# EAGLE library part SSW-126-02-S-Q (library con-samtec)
THROUGH-HOLE .025" SQ POST SOCKET Source: Samtec SSW.pdf
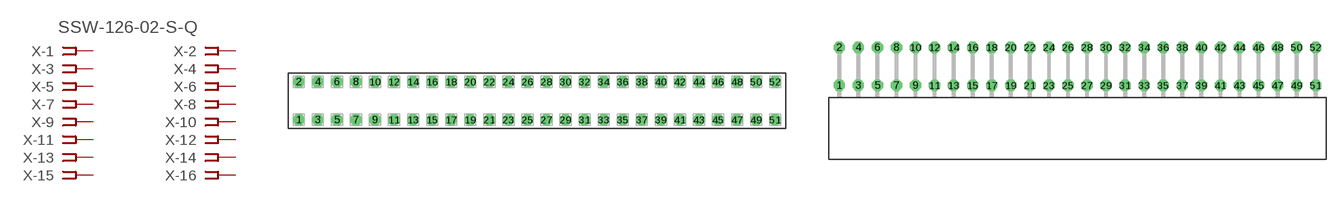
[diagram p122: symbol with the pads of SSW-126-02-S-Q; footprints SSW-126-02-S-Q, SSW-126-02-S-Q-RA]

Designator prefix X; gates -1=FPINV -2=FPIN -3=FPIN -4=FPIN -5=FPIN -6=FPIN -7=FPIN -8=FPIN -9=FPIN -10=FPIN -11=FPIN -12=FPIN -13=FPIN -14=FPIN -15=FPIN -16=FPIN -17=FPIN -18=FPIN -19=FPIN -20=FPIN -21=FPIN -22=FPIN -23=FPIN -24=FPIN -25=FPIN -26=FPIN -27=FPIN -28=FPIN -29=FPIN -30=FPIN -31=FPIN -32=FPIN -33=FPIN -34=FPIN -35=FPIN -36=FPIN -37=FPIN -38=FPIN -39=FPIN -40=FPIN -41=FPIN -42=FPIN -43=FPIN -44=FPIN -45=FPIN -46=FPIN -47=FPIN -48=FPIN -49=FPIN -50=FPIN -51=FPIN -52=FPIN

## SSW-126-02-S-Q (OC_FARNELL: unknown; OC_NEWARK: unknown)  [SSW-126-02-S-Q]
1  -1:1  pas
2  -2:1  pas
3  -3:1  pas
4  -4:1  pas
5  -5:1  pas
6  -6:1  pas
7  -7:1  pas
8  -8:1  pas
9  -9:1  pas
10  -10:1  pas
11  -11:1  pas
12  -12:1  pas
13  -13:1  pas
14  -14:1  pas
15  -15:1  pas
16  -16:1  pas
17  -17:1  pas
18  -18:1  pas
19  -19:1  pas
20  -20:1  pas
21  -21:1  pas
22  -22:1  pas
23  -23:1  pas
24  -24:1  pas
25  -25:1  pas
26  -26:1  pas
27  -27:1  pas
28  -28:1  pas
29  -29:1  pas
30  -30:1  pas
31  -31:1  pas
32  -32:1  pas
33  -33:1  pas
34  -34:1  pas
35  -35:1  pas
36  -36:1  pas
37  -37:1  pas
38  -38:1  pas
39  -39:1  pas
40  -40:1  pas
41  -41:1  pas
42  -42:1  pas
43  -43:1  pas
44  -44:1  pas
45  -45:1  pas
46  -46:1  pas
47  -47:1  pas
48  -48:1  pas
49  -49:1  pas
50  -50:1  pas
51  -51:1  pas
52  -52:1  pas

## SSW-126-02-S-QRA (OC_FARNELL: unknown; OC_NEWARK: unknown)  [SSW-126-02-S-Q-RA]
Pads as for SSW-126-02-S-Q

## Footprint SSW-126-02-S-Q (pad centres in mm)
THROUGH-HOLE .025" SQ POST SOCKET Source: Samtec SSW.pdf
drill 1 pad 1.5 octagon: 1 -31.75,-2.54; 2 -31.75,2.54; 3 -29.21,-2.54; 4 -29.21,2.54; 5 -26.67,-2.54; 6 -26.67,2.54; 7 -24.13,-2.54; 8 -24.13,2.54; 9 -21.59,-2.54; 10 -21.59,2.54; 11 -19.05,-2.54; 12 -19.05,2.54; 13 -16.51,-2.54; 14 -16.51,2.54; 15 -13.97,-2.54; 16 -13.97,2.54; 17 -11.43,-2.54; 18 -11.43,2.54; 19 -8.89,-2.54; 20 -8.89,2.54; 21 -6.35,-2.54; 22 -6.35,2.54; 23 -3.81,-2.54; 24 -3.81,2.54; 25 -1.27,-2.54; 26 -1.27,2.54; 27 1.27,-2.54; 28 1.27,2.54; 29 3.81,-2.54; 30 3.81,2.54; 31 6.35,-2.54; 32 6.35,2.54; 33 8.89,-2.54; 34 8.89,2.54; 35 11.43,-2.54; 36 11.43,2.54; 37 13.97,-2.54; 38 13.97,2.54; 39 16.51,-2.54; 40 16.51,2.54; 41 19.05,-2.54; 42 19.05,2.54; 43 21.59,-2.54; 44 21.59,2.54; 45 24.13,-2.54; 46 24.13,2.54; 47 26.67,-2.54; 48 26.67,2.54; 49 29.21,-2.54; 50 29.21,2.54; 51 31.75,-2.54; 52 31.75,2.54

## Footprint SSW-126-02-S-Q-RA (pad centres in mm)
THROUGH-HOLE .025" SQ POST SOCKET Source: Samtec SSW.pdf
drill 1 pad 1.5 octagon: 1 -31.75,1.524; 2 -31.75,6.604; 3 -29.21,1.524; 4 -29.21,6.604; 5 -26.67,1.524; 6 -26.67,6.604; 7 -24.13,1.524; 8 -24.13,6.604; 9 -21.59,1.524; 10 -21.59,6.604; 11 -19.05,1.524; 12 -19.05,6.604; 13 -16.51,1.524; 14 -16.51,6.604; 15 -13.97,1.524; 16 -13.97,6.604; 17 -11.43,1.524; 18 -11.43,6.604; 19 -8.89,1.524; 20 -8.89,6.604; 21 -6.35,1.524; 22 -6.35,6.604; 23 -3.81,1.524; 24 -3.81,6.604; 25 -1.27,1.524; 26 -1.27,6.604; 27 1.27,1.524; 28 1.27,6.604; 29 3.81,1.524; 30 3.81,6.604; 31 6.35,1.524; 32 6.35,6.604; 33 8.89,1.524; 34 8.89,6.604; 35 11.43,1.524; 36 11.43,6.604; 37 13.97,1.524; 38 13.97,6.604; 39 16.51,1.524; 40 16.51,6.604; 41 19.05,1.524; 42 19.05,6.604; 43 21.59,1.524; 44 21.59,6.604; 45 24.13,1.524; 46 24.13,6.604; 47 26.67,1.524; 48 26.67,6.604; 49 29.21,1.524; 50 29.21,6.604; 51 31.75,1.524; 52 31.75,6.604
